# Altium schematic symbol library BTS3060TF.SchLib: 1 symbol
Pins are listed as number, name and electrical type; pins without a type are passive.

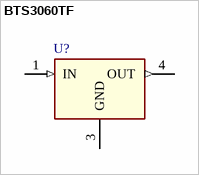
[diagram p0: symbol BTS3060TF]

## BTS3060TF
designator U?  (value not drawn)
HITFET Smart Low-Side Power Switch; Manufacturer: Infineon Technologies
footprint INF-PG-TO252-3-11_N_1
pins: 1 IN (in) "Input Pin", 3 GND (power) "Ground,Source For Power DMOS", 4 OUT (out) "Drain,Load Connection For Power DMOS"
